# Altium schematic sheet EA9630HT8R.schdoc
size 127 x 101 mm
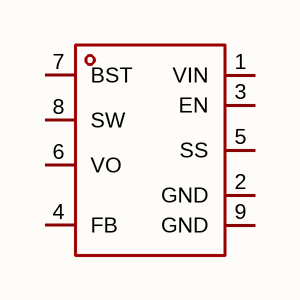
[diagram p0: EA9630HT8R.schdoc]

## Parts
U?  ea9630ht8r  [ESOP-8_L4.9-W3.9-P1.27-LS6.0-BL-EP-1]  (value not drawn)

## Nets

Not connected (* = marked no-connect by the designer): U? 1(VIN) 2(GND) 3(EN) 4(FB) 5(SS) 6(VO) 7(BST) 8(SW) 9(GND)

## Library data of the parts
U? = ea9630ht8r: 功能类型:降压型;工作电压:5V~61V;输出电压:790mV;输出电流:3A;输出类型:可调;; Manufacturer: everanalog(申风); AddInBom: yes; ModelId: 1edf17d9e1eb44b9aabe355eb95382d1; ModelTransform: 192.913,236.22,0,0,0,0,0,0,0; Function: 降压型; Voltage - Supply: 5V~61V; Output Voltage: 790mV; Output Current: 3A; Frequency - Switching: 500kHz; Synchronous Rectifier: 否; Number of Outputs: 1; Topology: 降压式; Quiescent Current: 400uA; Switch tube (built-in/external): 内置; Output Type: 可调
